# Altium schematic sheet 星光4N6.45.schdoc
size 292 x 204 mm; Device: A_A4_2; Symbol: A_A4_2; Name: A_A4; @Project Name: 星光4N贴片打板; REV: 6.1; Date: 2025/11/29; Sheet: 1/1; Draw By: 韩; Company: 流浪的星星; Convert to PCB: yes; Add into BOM: yes; @Page No: 1; @Page Count: 1; @Schematic Name: 星光4NV6.45; @Board Name: 星光4NV6.45加邮票; @Update Date: 2026-01-12; @Create Time: 21:23:01; @Update Time: 21:33:51; @Page Name: 星光4奥卡; @Create Date: 2026-01-12; Border: 0; Width: 1655; Height: 1170; Region Start: 1; X Region Count: 1; Y Region Count: 1; Title Block Position: 3; Title Block: 1
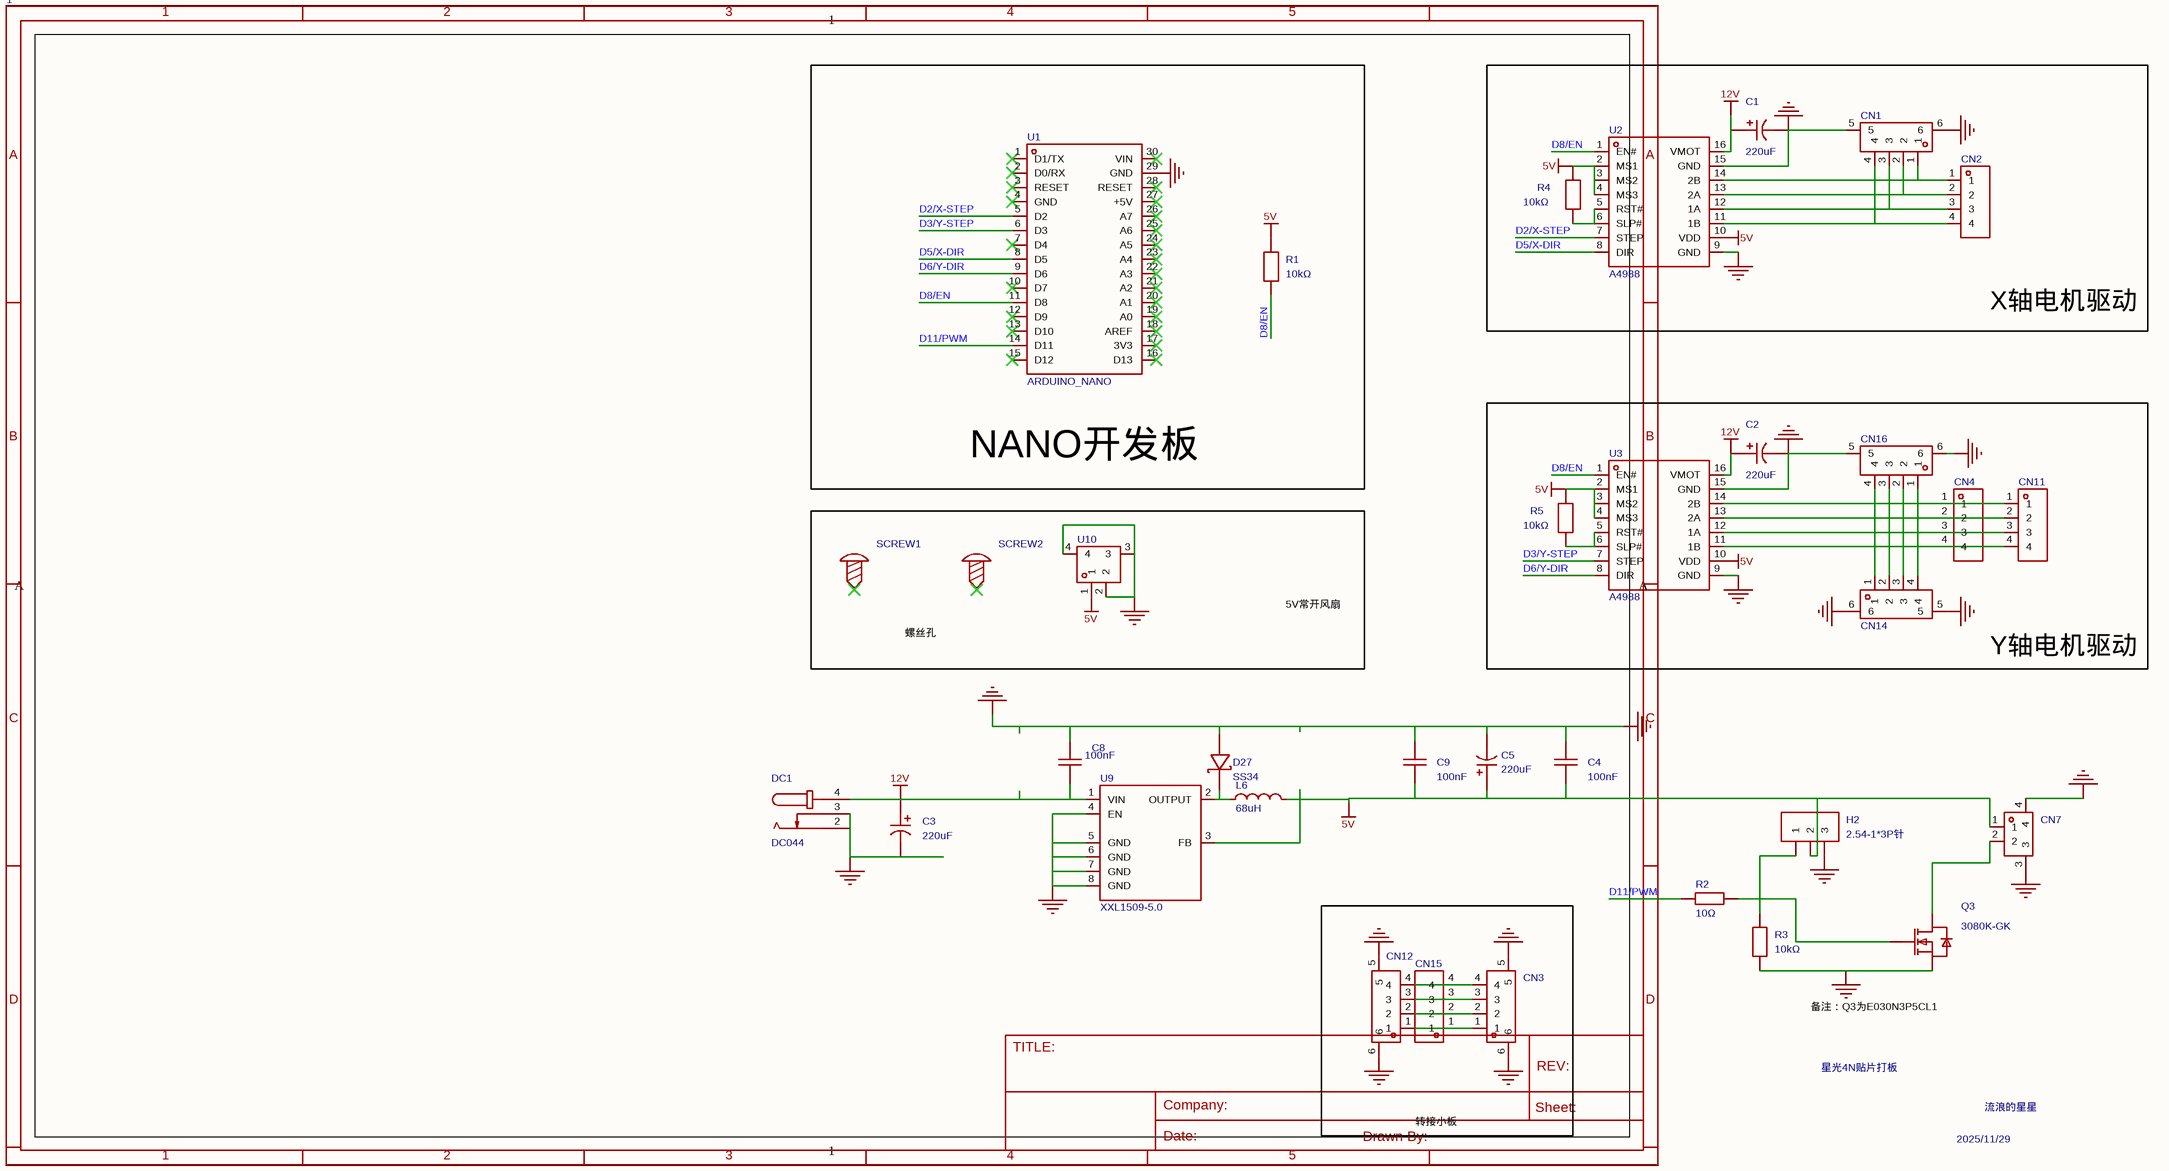
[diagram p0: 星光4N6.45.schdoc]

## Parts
C1  220uF  [CAP-SMD_BD6.3-L6.6-W6.6-FD-1]
C2  220uF  [CAP-SMD_BD6.3-L6.6-W6.6-FD-1]
C3  220uF  [CAP-SMD_BD6.3-L6.6-W6.6-FD-1]
C4  100nF  [C1206]
C5  220uF  [CAP-SMD_BD6.3-L6.6-W6.6-FD-1]
C8  100nF  [C1206]
C9  100nF  [C1206]
CN1  AFA07-S04ECC-00  [FPC-SMD_4P-P1.00_AFA07-S04ECC-00]  (value not drawn)
CN2  2.54-1*4P母  [HDR-TH_4P-P2.54-V-F]  (value not drawn)
CN3  10A20L04P  [FPC-SMD_4P-P1.00_10A20L04P]  (value not drawn)
CN4  2.54-1*4P母  [HDR-TH_4P-P2.54-V-F]  (value not drawn)
CN7  ZX-XH2.54-2PWT  [CONN-SMD_2P-P2.54_MEGASTAR_ZX-XH2.54-2PWT]  (value not drawn)
CN11  2.54-1*4P母  [HDR-TH_4P-P2.54-V-F]  (value not drawn)
CN12  AFA07-S04ECC-00  [FPC-SMD_4P-P1.00_AFA07-S04ECC-00]  (value not drawn)
CN14  10A20L04P  [FPC-SMD_4P-P1.00_10A20L04P]  (value not drawn)
CN15  2.54-1*4P母  [HDR-TH_4P-P2.54-V-F]  (value not drawn)
CN16  AFA07-S04ECC-00  [FPC-SMD_4P-P1.00_AFA07-S04ECC-00]  (value not drawn)
D27  SS34  [SMA_L4.3-W2.6-LS5.2-RD]
DC1  DC044  [DC-IN-TH_DC044]
H2  2.54-1*3P针  [HDR-TH_3P-P2.54-V-M-1]
L6  68uH  [IND-SMD_L7.1-W6.6_H5.0]
Q3  3080K-GK  [TO-252-2_L6.6-W6.1-P4.60-LS10.0-BR-CW]
R1  10kΩ  [R1206]
R2  10Ω  [R1206]
R3  10kΩ  [R1206]
R4  10kΩ  [R1206]
R5  10kΩ  [R1206]
SCREW1  (no value)  [M3螺丝]
SCREW2  (no value)  [M3螺丝]
U1  ARDUINO_NANO  [COMM-TH_ARDUINO_NANO]
U2  A4988  [DIP-16_L20.3-W15.2-P2.54_LS12.7_A4988]
U3  A4988  [DIP-16_L20.3-W15.2-P2.54_LS12.7_A4988]
U9  XXL1509-5.0  [SOIC-8_L4.9-W3.9-P1.27-LS6.0-BL]
U10  ZX-PH2.0-WT2P  [CONN-SMD_ZX-PH2.0-WT2P]  (value not drawn)

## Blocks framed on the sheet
NANO开发板: R1 U1
X轴电机驱动: C1 CN1 CN2 R4 U2
Y轴电机驱动: C2 CN4 CN11 CN14 CN16 R5 U3
转接小板: CN3 CN12 CN15

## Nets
5V: C4.2 C5.1 C9.2 CN7.1 H2.2 L6.1 R1.2 R4.2 R5.2 U2.2(MS1) U2.3(MS2) U2.4(MS3) U2.10(VDD) U3.2(MS1) U3.3(MS2) U3.4(MS3) U3.10(VDD) U9.3(FB) U10.1
12V: C1.1 C2.1 C3.1 C8.2 DC1.4 U2.16(VMOT) U3.16(VMOT) U9.1(VIN)
GND: C1.2 C2.2 C3.2 C4.1 C5.2 C8.1 C9.1 CN1.5 CN1.6 CN3.5 CN3.6 CN7.3 CN7.4 CN12.5 CN12.6 CN14.5 CN14.6 CN16.5 CN16.6 D27.2(A) DC1.2 DC1.3 H2.3 Q3.3(S) R3.1 U1.29(GND) U2.9(GND) U2.15(GND) U3.9(GND) U3.15(GND) U9.4(EN) U9.5(GND) U9.6(GND) U9.7(GND) U9.8(GND) U10.2 U10.3 U10.4
D2/X-STEP: U1.5(D2) U2.7(STEP)
D3/Y-STEP: U1.6(D3) U3.7(STEP)
D5/X-DIR: U1.8(D5) U2.8(DIR)
D6/Y-DIR: U1.9(D6) U3.8(DIR)
D8/EN: R1.1 U1.11(D8) U2.1(EN#) U3.1(EN#)
D11/PWM: R2.2 U1.14(D11)
NetCN1_1: CN1.1 CN2.1 U2.14(2B)
NetCN1_2: CN1.2 CN2.2 U2.13(2A)
NetCN1_3: CN1.3 CN2.3 U2.12(1A)
NetCN1_4: CN1.4 CN2.4 U2.11(1B)
NetCN3_1: CN3.1 CN12.1 CN15.1
NetCN3_2: CN3.2 CN12.2 CN15.2
NetCN3_3: CN3.3 CN12.3 CN15.3
NetCN3_4: CN3.4 CN12.4 CN15.4
NetCN4_1: CN4.1 CN11.1 CN14.4 CN16.1 U3.14(2B)
NetCN4_2: CN4.2 CN11.2 CN14.3 CN16.2 U3.13(2A)
NetCN4_3: CN4.3 CN11.3 CN14.2 CN16.3 U3.12(1A)
NetCN4_4: CN4.4 CN11.4 CN14.1 CN16.4 U3.11(1B)
NetCN7_2: CN7.2 Q3.2(D)
NetD27_1: D27.1(K) L6.2 U9.2(OUTPUT)
NetH2_1: H2.1 Q3.1(G) R2.1 R3.2
NetR4_1: R4.1 U2.5(RST#) U2.6(SLP#)
NetR5_1: R5.1 U3.5(RST#) U3.6(SLP#)

Not connected (* = marked no-connect by the designer): SCREW1 1*; SCREW2 1*; U1 1(D1/TX)* 2(D0/RX)* 3(RESET)* 4(GND)* 7(D4)* 10(D7)* 12(D9)* 13(D10)* 15(D12)* 16(D13)* 17(3V3)* 18(AREF)* 19(A0)* 20(A1)* 21(A2)* 22(A3)* 23(A4)* 24(A5)* 25(A6)* 26(A7)* 27(+5V)* 28(RESET)* 30(VIN)*

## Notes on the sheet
- 5V常开风扇
- 螺丝孔
- 备注：Q3为E030N3P5CL1

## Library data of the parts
C1-C3 C5 = JVJ16V220M6x8: 容值:220uF;精度:±20%;额定电压:16V;纹波电流:110mA@120Hz;; Manufacturer: 捷而瑞; AddInBom: yes; ModelId: 041333f082e2432d92aae8a67d233574; ModelTransform: 299.212,259.842,0,0,0,0,0,0,0; Tolerance: ±20%; Voltage Rating: 16V; Lifetime: 2000hrs@105℃
C4 C8 C9 = CL31B104KBCNNNC: 容值:100nF;精度:±10%;额定电压:50V;温度系数:X7R;; Manufacturer: SAMSUNG(三星); AddInBom: yes; ModelId: e4be705b945545a48e666415e3682bd8; ModelName: C1206_L3.2-W1.6-H1.3; ModelTransform: 125.984,62.992,0,0,0,0,0,0,0; Tolerance: ±10%; Voltage Rating: 50V; Temperature Coefficient: X7R
CN1 CN12 CN16 = AFA07-S04ECC-00: 锁定特性:抽屉式;触点类型:上接;触点数量:4P;间距:1mm;安装类型:卧贴;; Manufacturer: JS(钜硕电子); Symbol: FPCPull type Pick up H3.0mm; AddInBom: yes; ModelId: eb2037eadb4f4f60bc0cbc983aef8acd; ModelName: FPC-SMD_4P-P1.00_L11.0-W6.9-H2.5-AFA07-S04ECC-00; ModelTransform: 433.07,271.653,0,0,0,0,0,-76.773,0; Locking Feature: 抽屉式; Number of Contacts: 4P; Pitch: 1mm; FFC, FCB Thickness: 0.3mm
CN2 CN4 CN11 CN15 = 2.54-1*4P母: 插孔结构:1x4P;间距:2.54mm;行距:-;圆孔/方孔:方孔;安装类型:直插;排数:单排;总孔位数:4P;额定电流:3A;额定电压:-;插孔方向:顶部;塑高:-;触头材质:青铜;触头镀层:-;工作温度范围:-40℃~+105℃;焊接温度(最大值):-;; Manufacturer: BOOMELE(博穆精密); AddInBom: yes; ModelId: d187812051054f85879fcaa51a310d8e; ModelTransform: 419.6842,98.464,0,0,0,0,0,0,-118.11; Holes Structure: 1x4P; Pitch: 2.54mm; Circular Hole / Square Hole: 方孔; Number of Holes: 4P; Current Rating (Max): 3A; Holes Direction: 顶部
CN3 CN14 = 10A20L04P: 锁定特性:翻盖式;触点类型:下接;触点数量:4P;间距:1mm;; Manufacturer: HanElectricity(瀚源); AddInBom: yes; ModelId: 74aa4c8d5552434e99fa2d5862a4320d; ModelTransform: 354.7237,234.2515,0,0,0,0,0,-62.165,0; Locking Feature: 翻盖式; Number of Contacts: 4P; Pitch: 1mm
CN7 = ZX-XH2.54-2PWT: 插针结构:1x2P;间距:2.5mm;安装方式:卧贴;参考系列:XH;总PIN数:2P;排数:1;每排PIN数:2;行距:-;额定电流:3A;触头材质:黄铜;触头镀层:锡;工作温度:-25℃~+85℃;; Manufacturer: Megastar(兆星); AddInBom: yes; ModelId: 905258e72c284f268702918f5ed0d447; ModelTransform: 393.7,413.385,0,0,0,0,0,0.001,0; Pins Structure: 1x2P; Pitch: 2.5mm; Reference Series: XH; Number of PINs Per Row: 2; Current Rating: 3A; Voltage Rating: 250V; Supplementary Features: 辅助焊脚; Z-Height of the Board: 6.2mm; X-Length of Bottom Edge on Board (Spacing Line): 10mm; Y-Width of Bottom Edge on Board: 10.5mm
D27 = SS34_C8678: 二极管配置:独立式;正向压降(Vf):550mV@3A;直流反向耐压(Vr):40V;整流电流:3A;; Manufacturer: MDD(辰达半导体); AddInBom: yes; ModelId: e3551acb3c5a4975a5e9d36087fe1fa2; ModelTransform: 185.039,102.362,0,0,0,0,0,0,0; Diode Configuration: 独立式; Voltage - DC Reverse(Vr): 40V; Current - Rectified: 3A; Reverse Leakage Current (Ir): 500uA@40V; Operating Junction Temperature Range: -55℃~+125℃
DC1 = DC044: 连接器类型:DC电源插座;安装方式:弯插;触点内径:2mm;触点外径:6mm;额定电流:1A;额定电压:30V;工作温度范围:-25℃~+70℃;; Manufacturer: SHOU HAN(首韩); AddInBom: yes; ModelId: b408fe5c839c4e2494e641f3d5bfb7bc; ModelTransform: 452.755,374.015,0,0,0,0,-173.858,7.872,-118.11; Connector Type: DC电源插座; Inside Contact Diameter: 2mm; Outside Contact Diameter: 6mm; Current Rating (Max): 1A; Voltage Rating (Max): 30V
H2 = 2.54-1*3P针: 插针结构:1x3P;间距:2.54mm;行距:-;圆针/方针:方针;安装方式:直插;排数:单排;总PIN位数:3P;额定电流:3A;额定电压:-;配合针长度:6mm;塑高:2.5mm;端接针长度:3mm;触头材质:黄铜;触头镀层:金;工作温度:-40℃~+105℃;颜色:黑色;; Manufacturer: BOOMELE(博穆精密); Symbol: Header-Male-2.54_1x3; AddInBom: yes; ModelId: 94a8ffe137b6410295cb18cd3ffd99db; ModelName: HDR-M-2.54_1x3; ModelTransform: 299.9994,100,0,0,0,0,0,0,-118.11; Pin Structure: 1x3P; Pitch: 2.54mm; Circluar Pins/Square Pins: 方针; Current Rating: 3A
L6 = PSPMAA0605H-680M-IGF: 电感值:68uH;精度:±20%;额定电流:1.5A;饱和电流(Isat):2A;类型:-;; Manufacturer: PROD(谱罗德); Channel ID: $1e43394; AddInBom: yes; ModelId: 42305e89796f47b49312a685ea93d494; ModelName: IND-SMD_L7.1-W6.6-H5.0; ModelTransform: 275.59,259.88137,0,0,0,0,0,-0.551,0; Tolerance: ±20%; Current Rating: 1.5A; Current - Saturation(Isat): 2A; DC Resistance(DCR): 256mΩ
Q3 = 3080K-GK: 数量:1个N沟道;漏源电压(Vdss):30V;连续漏极电流(Id):80A;导通电阻(RDS(on)):9mΩ@4.5V;耗散功率(Pd):81W;阈值电压(Vgs(th)):2.5V@250uA;; Manufacturer: GOODWORK(固得沃克); AddInBom: yes; ModelId: 2bfbfbb77002446c96d8a76a432e0188; ModelTransform: 246.80147,383.8575,0,90,0,0,-31.302,0.003,0; Number: 1个N沟道; Drain to Source Voltage: 30V; Current - Continuous Drain(Id): 80A; Pd - Power Dissipation: 81W; Gate Charge(Qg): 45nC@10V; Input Capacitance(Ciss): 2.153nF; Reverse Transfer Capacitance (Crss@Vds): 287pF; Type: N沟道; Output Capacitance(Coss): 327pF
R1 R3-R5 = FRR1206J103 TS: 电阻类型:厚膜电阻;阻值:10kΩ;精度:±5%;功率:250mW;工作电压:200V;温度系数:±100ppm/℃;; Manufacturer: FOJAN(富捷); AddInBom: yes; ModelId: 89a1f13db2384da588040e0b3c55bf66; ModelName: R1206_L3.2-W1.6-H0.6; ModelTransform: 125.984,62.992,0,0,0,0,0,0,0; Tolerance: ±5%; Power(Watts): 250mW; Voltage-Supply(Max): 200V
R2 = 1206W4F100JT5E: 电阻类型:厚膜电阻;阻值:10Ω;精度:±1%;功率:250mW;工作电压:200V;温度系数:±400ppm/℃;; Manufacturer: UNI-ROYAL(厚声); AddInBom: yes; ModelId: 89a1f13db2384da588040e0b3c55bf66; ModelName: R1206_L3.2-W1.6-H0.6; ModelTransform: 125.984,62.992,0,0,0,0,0,0,0; Tolerance: ±1%; Power(Watts): 250mW; Voltage-Supply(Max): 200V
SCREW1 SCREW2 = M3螺丝: ConvertToPcb: yes; SymbolName: 螺丝孔
U1 = ARDUINO_NANO: AddInBom: yes; ModelId: 569460a3ee974a868db0f4d8fd87e38b; ModelTransform: 699.9986,1784.14604,0,270,0,0,-42.323,0,-137.795
U2 U3 = A4988: AddInBom: yes; ModelId: 91b5bbb4c7ad4d72991c4bfd5544d532; ModelTransform: 599.9988,799.998,0,0,0,0,0,0,-196.85
U9 = XXL1509-5.0: 功能类型:降压型;工作电压:4.5V~40V;输出电压:4.8V~5.2V;输出电流:3A;输出类型:固定;; Manufacturer: XBLW(芯伯乐); AddInBom: yes; ModelId: e81d2f7d937b4a6ab1dca543ff5d56a4; ModelName: SOIC-8_L4.9-W3.9-H1.7-LS6.0-P1.27; ModelTransform: 189.751,236.22,0,0,0,0,0.0005,0.0005,0; Function: 降压型; Output Current: 3A; Frequency - Switching: 150kHz; Synchronous Rectifier: 否; Number of Outputs: 1; Topology: 降压式; Quiescent Current: 5mA; Switch tube (built-in/external): 内置; Output Type: 固定
U10 = ZX-PH2.0-WT2P: 插针结构:1x2P;间距:2mm;安装方式:卧贴;参考系列:PH;总PIN数:2P;排数:1;每排PIN数:2;行距:-;额定电流:2A;触头材质:黄铜;触头镀层:锡;工作温度:-25℃~+85℃;; Manufacturer: Megastar(兆星); AddInBom: yes; ModelId: 06be73072cd946eca23225be08c59a5b; ModelTransform: 314.96,334.645,0,0,0,0,-0.001,-9.406,0; Pins Structure: 1x2P; Pitch: 2mm; Reference Series: PH; Number of PINs Per Row: 2; Current Rating: 2A; Voltage Rating: 250V; Plastic Material: LCP; Supplementary Features: 辅助焊脚; Z-Height of the Board: 5.6mm; X-Length of Bottom Edge on Board (Spacing Line): 8mm; Y-Width of Bottom Edge on Board: 7.59mm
